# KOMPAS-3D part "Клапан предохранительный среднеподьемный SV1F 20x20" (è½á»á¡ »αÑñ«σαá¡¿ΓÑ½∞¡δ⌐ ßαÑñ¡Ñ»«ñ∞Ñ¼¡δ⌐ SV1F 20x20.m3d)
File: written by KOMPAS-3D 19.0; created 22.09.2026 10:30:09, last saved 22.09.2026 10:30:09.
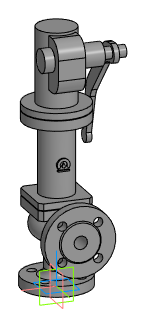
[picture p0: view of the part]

Document properties: Автор: Евгений; Полное имя файла: Z:\3.Личные\sachek\Dendor\_3D для проектировщиков\5.8 SV1F. Клапан предохранительный среднеподьемный\SV1F_STP\Клапан предохранительный среднеподьемный SV1F 20x20.m3d

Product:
- Part/product: Клапан предохранительный среднеподьемный SV1F 20x20
    Масса: 15.0136

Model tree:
1. Операция без истории:1  (labels: Клапан предохранительный среднеподьемный SV1F 20x20)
